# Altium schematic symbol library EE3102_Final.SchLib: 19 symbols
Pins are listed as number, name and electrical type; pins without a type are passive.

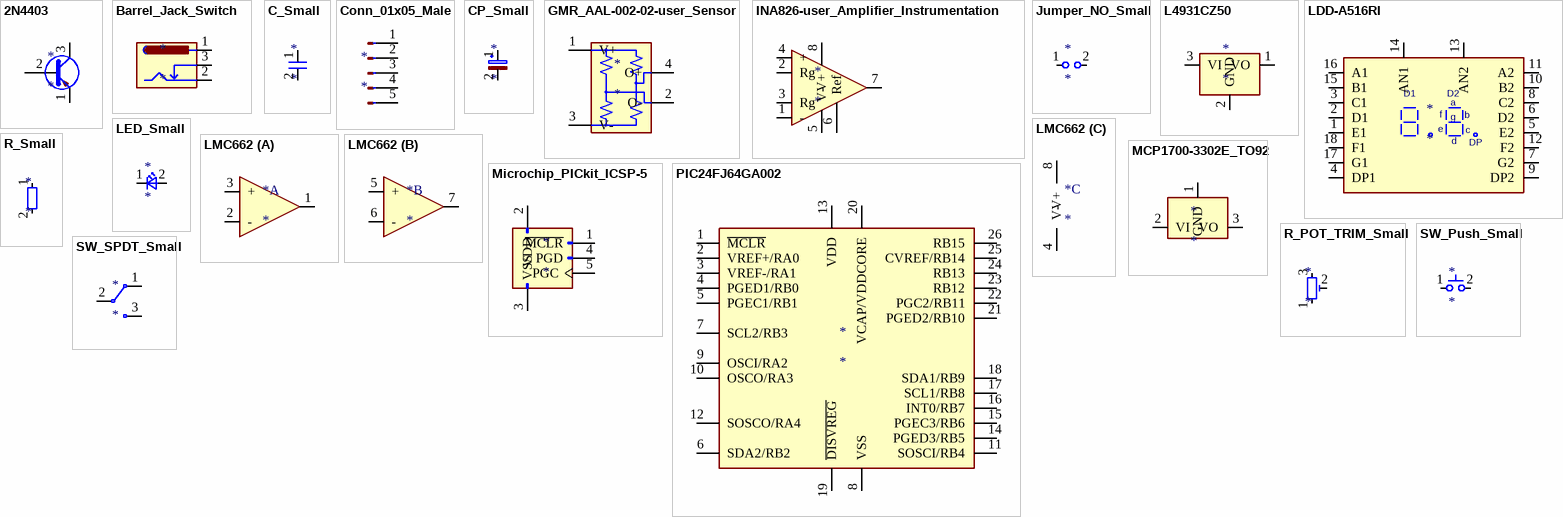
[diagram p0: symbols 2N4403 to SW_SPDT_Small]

## 2N4403
designator *
pins: 1 E, 2 B, 3 C

## Barrel_Jack_Switch
designator *
pins: 1, 2, 3

## C_Small
designator *
pins: 1, 2

## Conn_01x05_Male
designator *
pins: 1 Pin_1, 2 Pin_2, 3 Pin_3, 4 Pin_4, 5 Pin_5

## CP_Small
designator *
pins: 1, 2

## GMR_AAL-002-02-user_Sensor
designator *
pins: 1 V+, 2 O-, 3 V-, 4 O+

## INA826-user_Amplifier_Instrumentation
designator *
pins: 1 -, 2 Rg, 3 Rg, 4 +, 5 V-, 6 Ref, 7, 8 V+

## Jumper_NO_Small
designator *
pins: 1, 2

## L4931CZ50
designator *
pins: 1 VO, 2 GND, 3 VI

## LDD-A516RI
designator *
pins: 1 E1, 2 D1, 3 C1, 4 DP1, 5 E2, 6 D2, 7 G2, 8 C2, 9 DP2, 10 B2, 11 A2, 12 F2, 13 AN2, 14 AN1, 15 B1, 16 A1, 17 G1, 18 F1

## LED_Small
designator *
pins: 1 K, 2 A

## LMC662
designator *
part A pins: 1, 2 -, 3 +
part B pins: 5 +, 6 -, 7
part C pins: 4 V-, 8 V+

## MCP1700-3302E_TO92
designator *
pins: 1 GND, 2 VI, 3 VO

## Microchip_PICkit_ICSP-5
designator *
pins: 1 ~{MCLR}, 2 VDD, 3 VSS, 4 PGD, 5 PGC

## PIC24FJ64GA002
designator *
pins: 1 ~{MCLR}, 2 VREF+/RA0, 3 VREF-/RA1, 4 PGED1/RB0, 5 PGEC1/RB1, 6 SDA2/RB2, 7 SCL2/RB3, 8 VSS, 9 OSCI/RA2, 10 OSCO/RA3, 11 SOSCI/RB4, 12 SOSCO/RA4, 13 VDD, 14 PGED3/RB5, 15 PGEC3/RB6, 16 INT0/RB7, 17 SCL1/RB8, 18 SDA1/RB9, 19 ~{DISVREG}, 20 VCAP/VDDCORE, 21 PGED2/RB10, 22 PGC2/RB11, 23 RB12, 24 RB13, 25 CVREF/RB14, 26 RB15, 27 VSS hidden, 28 VDD hidden

## R_POT_TRIM_Small
designator *
pins: 1 CCW, 2 W, 3 CW

## R_Small
designator *
pins: 1, 2

## SW_Push_Small
designator *
pins: 1, 2

## SW_SPDT_Small
designator *
pins: 1 A, 2 B, 3 C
